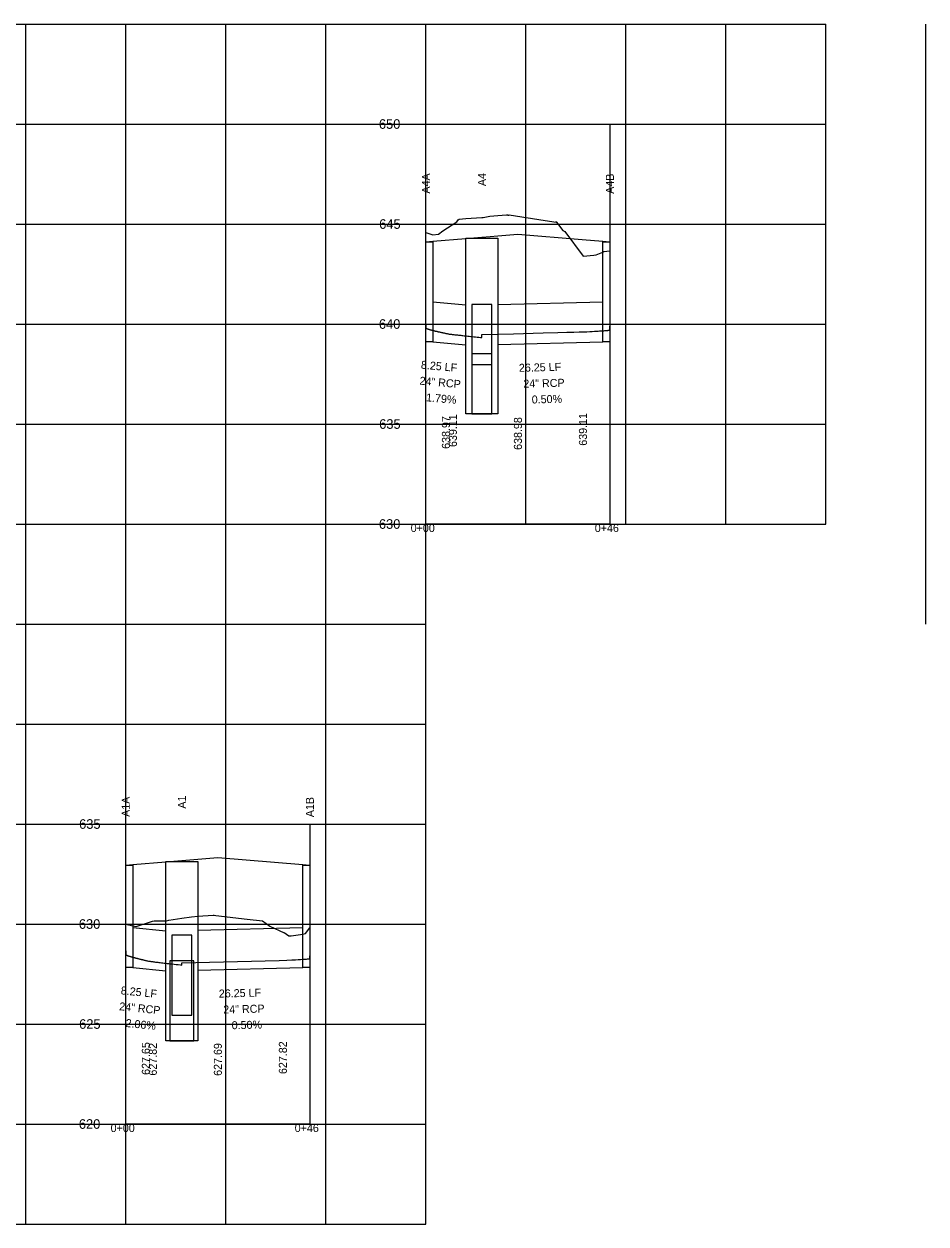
# Model space of a CAD drawing. Extents: x 2252703 to 2264864, y 13787568 to 13790989.
# Drawn here: x 2264638.2 to 2264863.7, y 13787568.1 to 13787868.1 of the extents above; entities that cross this region are included whole.
import ezdxf

# ---------------------------------------------------------------- set-up
doc = ezdxf.new("R2010")
doc.units = 0
for name, color, linetype in [('blank4', 7, 'Continuous'), ('BORD_grid_bottom_major_5int', 7, 'Continuous'), ('D_DRN_PROF_HGL', 7, 'Continuous'), ('D_PROF_1', 7, 'Continuous'), ('D_PROF_NOTES_1', 7, 'Continuous'), ('Default', 7, 'Continuous'), ('Drain_PipeInside', 7, 'Continuous'), ('E_Terrain', 7, 'Continuous'), ('Inlet', 7, 'Continuous'), ('z - Construction', 7, 'Continuous')]:
    doc.layers.add(name, color=color, linetype=linetype)

msp = doc.modelspace()

# ---------------------------------------------------------------- linework, layer by layer
at = {"layer": 'blank4'}
for points in [[(2264738.67, 13787743.09), (2264738.67, 13787843.09), (2264784.67, 13787843.09), (2264784.67, 13787743.09)], [(2264663.67, 13787593.09), (2264663.67, 13787668.09), (2264709.67, 13787668.09), (2264709.67, 13787593.09)]]:
    msp.add_lwpolyline(points, close=True, dxfattribs=at)
at = {"layer": 'BORD_grid_bottom_major_5int'}
for p, q in [((2264413.67, 13787868.09), (2264838.67, 13787868.09)), ((2264638.67, 13787568.09), (2264638.67, 13787868.09)), ((2264663.67, 13787568.09), (2264663.67, 13787868.09)), ((2264688.67, 13787568.09), (2264688.67, 13787868.09)), ((2264713.67, 13787568.09), (2264713.67, 13787868.09)), ((2264738.67, 13787568.09), (2264738.67, 13787868.09)), ((2264763.67, 13787743.09), (2264763.67, 13787868.09)), ((2264788.67, 13787743.09), (2264788.67, 13787868.09)), ((2264813.67, 13787743.09), (2264813.67, 13787868.09)), ((2264838.67, 13787743.09), (2264838.67, 13787868.09)), ((2264863.67, 13787718.09), (2264863.67, 13787868.09)), ((2264413.67, 13787843.09), (2264838.67, 13787843.09)), ((2264413.67, 13787818.09), (2264838.67, 13787818.09)), ((2264413.67, 13787793.09), (2264838.67, 13787793.09)), ((2264413.67, 13787768.09), (2264838.67, 13787768.09)), ((2264413.67, 13787743.09), (2264838.67, 13787743.09)), ((2264413.67, 13787718.09), (2264738.67, 13787718.09)), ((2264413.67, 13787693.09), (2264738.67, 13787693.09)), ((2264413.67, 13787668.09), (2264738.67, 13787668.09)), ((2264413.67, 13787643.09), (2264738.67, 13787643.09)), ((2264413.67, 13787618.09), (2264738.67, 13787618.09)), ((2264413.67, 13787593.09), (2264738.67, 13787593.09)), ((2264413.67, 13787568.09), (2264738.67, 13787568.09))]:
    msp.add_line(p, q, dxfattribs=at)
at = {"layer": 'D_DRN_PROF_HGL'}
for p, q in [((2264752.67, 13787789.71), (2264752.67, 13787790.46)), ((2264677.67, 13787632.83), (2264677.67, 13787633.39))]:
    msp.add_line(p, q, dxfattribs=at)
for points in [[(2264738.67, 13787793.15), (2264738.67, 13787792.13), (2264738.67, 13787792.12), (2264738.67, 13787792.12), (2264738.67, 13787792.11), (2264738.68, 13787792.11), (2264738.68, 13787792.1), (2264738.68, 13787792.1), (2264738.69, 13787792.09), (2264738.69, 13787792.08), (2264738.7, 13787792.08), (2264738.7, 13787792.07), (2264738.71, 13787792.07), (2264738.71, 13787792.06), (2264738.72, 13787792.05), (2264738.73, 13787792.05), (2264738.74, 13787792.04), (2264738.75, 13787792.03), (2264738.76, 13787792.03), (2264738.77, 13787792.02), (2264738.78, 13787792.01), (2264738.8, 13787792.01), (2264738.81, 13787792), (2264738.82, 13787791.99), (2264738.84, 13787791.98), (2264738.85, 13787791.98), (2264738.87, 13787791.97), (2264738.89, 13787791.96), (2264738.91, 13787791.95), (2264738.93, 13787791.94), (2264738.95, 13787791.93), (2264738.97, 13787791.92), (2264738.99, 13787791.92), (2264739.01, 13787791.91), (2264739.04, 13787791.9), (2264739.06, 13787791.89), (2264739.09, 13787791.88), (2264739.11, 13787791.87), (2264739.14, 13787791.86), (2264739.17, 13787791.85), (2264739.2, 13787791.84), (2264739.23, 13787791.83), (2264739.26, 13787791.82), (2264739.3, 13787791.81), (2264739.33, 13787791.79), (2264739.37, 13787791.78), (2264739.4, 13787791.77), (2264739.44, 13787791.76), (2264739.48, 13787791.75), (2264739.52, 13787791.74), (2264739.56, 13787791.72), (2264739.6, 13787791.71), (2264739.65, 13787791.7), (2264739.69, 13787791.68), (2264739.74, 13787791.67), (2264739.79, 13787791.66), (2264739.84, 13787791.64), (2264739.89, 13787791.63), (2264739.94, 13787791.61), (2264740, 13787791.6), (2264740.05, 13787791.59), (2264740.11, 13787791.57), (2264740.17, 13787791.55), (2264740.23, 13787791.54), (2264740.29, 13787791.52), (2264740.36, 13787791.51), (2264740.42, 13787791.49), (2264740.49, 13787791.47), (2264740.56, 13787791.45), (2264740.63, 13787791.44), (2264740.71, 13787791.42), (2264740.78, 13787791.4), (2264740.86, 13787791.38), (2264740.94, 13787791.36), (2264741.02, 13787791.34), (2264741.11, 13787791.32), (2264741.19, 13787791.3), (2264741.28, 13787791.28), (2264741.37, 13787791.26), (2264741.47, 13787791.24), (2264741.56, 13787791.21), (2264741.66, 13787791.19), (2264741.76, 13787791.17), (2264741.87, 13787791.14), (2264741.97, 13787791.12), (2264742.08, 13787791.1), (2264742.2, 13787791.07), (2264742.31, 13787791.04), (2264742.43, 13787791.02), (2264742.56, 13787790.99), (2264742.68, 13787790.96), (2264742.81, 13787790.94), (2264742.94, 13787790.91), (2264743.08, 13787790.88), (2264743.22, 13787790.85), (2264743.37, 13787790.82), (2264743.52, 13787790.78), (2264743.67, 13787790.75), (2264743.83, 13787790.72), (2264743.99, 13787790.68), (2264744.16, 13787790.65), (2264744.33, 13787790.61), (2264744.5, 13787790.58), (2264744.69, 13787790.56), (2264744.87, 13787790.54), (2264745.07, 13787790.52), (2264745.27, 13787790.5), (2264745.47, 13787790.47), (2264745.68, 13787790.45), (2264745.9, 13787790.42), (2264746.13, 13787790.4), (2264746.36, 13787790.37), (2264746.6, 13787790.35), (2264746.85, 13787790.32), (2264747.11, 13787790.29), (2264747.37, 13787790.26), (2264747.65, 13787790.23), (2264747.93, 13787790.2), (2264748.23, 13787790.17), (2264748.53, 13787790.14), (2264748.85, 13787790.1), (2264749.18, 13787790.07), (2264749.52, 13787790.03), (2264749.87, 13787790), (2264750.24, 13787789.96), (2264750.63, 13787789.92), (2264751.03, 13787789.88), (2264751.45, 13787789.84), (2264751.89, 13787789.79), (2264752.34, 13787789.75), (2264752.67, 13787789.71)], [(2264752.67, 13787790.46), (2264760.6, 13787790.67), (2264768.01, 13787790.86), (2264771.61, 13787790.95), (2264773.94, 13787791.02), (2264775.63, 13787791.06), (2264776.94, 13787791.1), (2264778, 13787791.13), (2264778.87, 13787791.16), (2264779.61, 13787791.2), (2264780.24, 13787791.24), (2264780.79, 13787791.27), (2264781.27, 13787791.3), (2264781.69, 13787791.32), (2264782.06, 13787791.35), (2264782.39, 13787791.37), (2264782.68, 13787791.39), (2264782.94, 13787791.41), (2264783.17, 13787791.42), (2264783.38, 13787791.44), (2264783.57, 13787791.45), (2264783.73, 13787791.47), (2264783.88, 13787791.48), (2264784.01, 13787791.49), (2264784.12, 13787791.5), (2264784.23, 13787791.51), (2264784.31, 13787791.52), (2264784.39, 13787791.53), (2264784.46, 13787791.54), (2264784.51, 13787791.55), (2264784.56, 13787791.55), (2264784.6, 13787791.56), (2264784.63, 13787791.57), (2264784.65, 13787791.57), (2264784.66, 13787791.58), (2264784.67, 13787791.58), (2264784.67, 13787791.59), (2264784.67, 13787792.54)], [(2264663.67, 13787636.41), (2264663.67, 13787635.46), (2264663.67, 13787635.45), (2264663.67, 13787635.45), (2264663.68, 13787635.44), (2264663.68, 13787635.44), (2264663.68, 13787635.43), (2264663.69, 13787635.42), (2264663.69, 13787635.42), (2264663.7, 13787635.41), (2264663.7, 13787635.41), (2264663.71, 13787635.4), (2264663.72, 13787635.39), (2264663.73, 13787635.39), (2264663.74, 13787635.38), (2264663.74, 13787635.37), (2264663.76, 13787635.37), (2264663.77, 13787635.36), (2264663.78, 13787635.35), (2264663.79, 13787635.34), (2264663.8, 13787635.33), (2264663.82, 13787635.33), (2264663.83, 13787635.32), (2264663.85, 13787635.31), (2264663.87, 13787635.3), (2264663.88, 13787635.29), (2264663.9, 13787635.28), (2264663.92, 13787635.28), (2264663.94, 13787635.27), (2264663.96, 13787635.26), (2264663.99, 13787635.25), (2264664.01, 13787635.24), (2264664.03, 13787635.23), (2264664.06, 13787635.22), (2264664.09, 13787635.21), (2264664.11, 13787635.2), (2264664.14, 13787635.19), (2264664.17, 13787635.17), (2264664.2, 13787635.16), (2264664.23, 13787635.15), (2264664.27, 13787635.14), (2264664.3, 13787635.13), (2264664.34, 13787635.11), (2264664.38, 13787635.1), (2264664.41, 13787635.09), (2264664.45, 13787635.08), (2264664.49, 13787635.06), (2264664.54, 13787635.05), (2264664.58, 13787635.04), (2264664.63, 13787635.02), (2264664.67, 13787635.01), (2264664.72, 13787634.99), (2264664.77, 13787634.98), (2264664.82, 13787634.96), (2264664.87, 13787634.94), (2264664.93, 13787634.93), (2264664.99, 13787634.91), (2264665.04, 13787634.89), (2264665.1, 13787634.88), (2264665.17, 13787634.86), (2264665.23, 13787634.84), (2264665.3, 13787634.82), (2264665.37, 13787634.8), (2264665.44, 13787634.78), (2264665.51, 13787634.76), (2264665.58, 13787634.74), (2264665.66, 13787634.72), (2264665.74, 13787634.7), (2264665.82, 13787634.68), (2264665.9, 13787634.66), (2264665.99, 13787634.63), (2264666.08, 13787634.61), (2264666.17, 13787634.59), (2264666.27, 13787634.56), (2264666.36, 13787634.54), (2264666.47, 13787634.51), (2264666.57, 13787634.49), (2264666.68, 13787634.46), (2264666.79, 13787634.43), (2264666.9, 13787634.4), (2264667.02, 13787634.37), (2264667.14, 13787634.34), (2264667.26, 13787634.31), (2264667.39, 13787634.28), (2264667.53, 13787634.25), (2264667.66, 13787634.21), (2264667.81, 13787634.18), (2264667.95, 13787634.15), (2264668.1, 13787634.11), (2264668.26, 13787634.07), (2264668.42, 13787634.03), (2264668.59, 13787633.99), (2264668.76, 13787633.95), (2264668.94, 13787633.91), (2264669.12, 13787633.87), (2264669.32, 13787633.82), (2264669.51, 13787633.79), (2264669.72, 13787633.76), (2264669.93, 13787633.73), (2264670.15, 13787633.71), (2264670.38, 13787633.68), (2264670.62, 13787633.65), (2264670.87, 13787633.62), (2264671.12, 13787633.59), (2264671.39, 13787633.55), (2264671.67, 13787633.52), (2264671.96, 13787633.49), (2264672.26, 13787633.45), (2264672.58, 13787633.41), (2264672.91, 13787633.37), (2264673.26, 13787633.33), (2264673.62, 13787633.29), (2264674, 13787633.25), (2264674.4, 13787633.2), (2264674.82, 13787633.15), (2264675.26, 13787633.1), (2264675.73, 13787633.05), (2264676.22, 13787632.99), (2264676.74, 13787632.93), (2264677.3, 13787632.87), (2264677.67, 13787632.83)], [(2264677.67, 13787633.39), (2264702.02, 13787634), (2264703.92, 13787634.05), (2264705.17, 13787634.12), (2264706.07, 13787634.17), (2264706.76, 13787634.21), (2264707.3, 13787634.24), (2264707.74, 13787634.27), (2264708.11, 13787634.29), (2264708.41, 13787634.31), (2264708.66, 13787634.33), (2264708.86, 13787634.34), (2264709.04, 13787634.36), (2264709.18, 13787634.37), (2264709.3, 13787634.38), (2264709.4, 13787634.39), (2264709.48, 13787634.4), (2264709.55, 13787634.41), (2264709.59, 13787634.41), (2264709.63, 13787634.42), (2264709.65, 13787634.43), (2264709.66, 13787634.43), (2264709.66, 13787634.44), (2264709.67, 13787634.44), (2264709.67, 13787635.13)]]:
    msp.add_lwpolyline(points, dxfattribs=at)
at = {"layer": 'D_PROF_1'}
for points in [[(2264738.67, 13787813.66), (2264740.42, 13787813.8), (2264740.42, 13787813.8), (2264748.67, 13787814.48), (2264748.67, 13787814.48), (2264752.67, 13787814.81), (2264752.67, 13787814.81), (2264754.77, 13787814.98), (2264756.67, 13787815.13), (2264756.67, 13787815.13), (2264761.67, 13787815.54), (2264777.77, 13787814.22), (2264782.92, 13787813.8), (2264782.92, 13787813.8), (2264784.67, 13787813.66)], [(2264663.67, 13787657.83), (2264665.42, 13787657.97), (2264665.42, 13787657.97), (2264673.67, 13787658.65), (2264673.67, 13787658.65), (2264677.67, 13787658.97), (2264677.67, 13787658.97), (2264681.67, 13787659.3), (2264681.67, 13787659.3), (2264686.67, 13787659.71), (2264686.67, 13787659.71), (2264707.92, 13787657.97), (2264707.92, 13787657.97), (2264709.67, 13787657.83), (2264709.67, 13787657.83)]]:
    msp.add_lwpolyline(points, dxfattribs=at)
at = {"layer": 'Drain_PipeInside'}
for p, q in [((2264740.42, 13787798.66), (2264748.67, 13787797.92)), ((2264756.67, 13787798), (2264782.92, 13787798.66)), ((2264740.42, 13787788.66), (2264748.67, 13787787.92)), ((2264756.67, 13787788), (2264782.92, 13787788.66)), ((2264665.42, 13787642.21), (2264673.67, 13787641.36)), ((2264681.67, 13787641.56), (2264707.92, 13787642.21)), ((2264665.42, 13787632.21), (2264673.67, 13787631.36)), ((2264681.67, 13787631.56), (2264707.92, 13787632.21))]:
    msp.add_line(p, q, dxfattribs=at)
for points in [[(2264750.17, 13787782.94), (2264755.17, 13787782.94), (2264755.17, 13787797.94), (2264750.17, 13787797.94)], [(2264750.17, 13787770.61), (2264755.17, 13787770.61), (2264755.17, 13787785.61), (2264750.17, 13787785.61)], [(2264675.17, 13787620.32), (2264680.17, 13787620.32), (2264680.17, 13787640.32), (2264675.17, 13787640.32)], [(2264674.67, 13787613.88), (2264680.67, 13787613.88), (2264680.67, 13787633.88), (2264674.67, 13787633.88)]]:
    msp.add_lwpolyline(points, close=True, dxfattribs=at)
at = {"layer": 'E_Terrain'}
for points in [[(2264738.67, 13787815.97), (2264740.4, 13787815.42), (2264740.42, 13787815.42), (2264740.42, 13787815.42), (2264741.79, 13787815.59), (2264742.93, 13787816.38), (2264746.39, 13787818.61), (2264746.71, 13787819.12), (2264746.96, 13787819.33), (2264748.67, 13787819.43), (2264748.67, 13787819.43), (2264752.67, 13787819.68), (2264752.67, 13787819.68), (2264753.02, 13787819.7), (2264754.62, 13787820.02), (2264756.67, 13787820.2), (2264756.67, 13787820.2), (2264758.79, 13787820.38), (2264759.05, 13787820.35), (2264759.13, 13787820.34), (2264759.4, 13787820.34), (2264759.48, 13787820.36), (2264768.49, 13787818.97), (2264771.24, 13787818.58), (2264771.24, 13787818.69), (2264771.32, 13787818.52), (2264772.93, 13787816.45), (2264773.37, 13787816.23), (2264778.02, 13787810.05), (2264780.65, 13787810.34), (2264781.26, 13787810.36), (2264782.92, 13787811.08), (2264782.92, 13787811.08), (2264783.15, 13787811.18), (2264784.67, 13787811.42)], [(2264663.67, 13787643.05), (2264665.42, 13787642.66), (2264665.42, 13787642.66), (2264666.23, 13787642.48), (2264670.36, 13787643.8), (2264670.75, 13787643.85), (2264673.67, 13787643.91), (2264673.67, 13787643.91), (2264673.8, 13787643.92), (2264674.41, 13787644.09), (2264677.67, 13787644.55), (2264677.67, 13787644.55), (2264680.12, 13787644.89), (2264681.67, 13787645.01), (2264681.67, 13787645.01), (2264685.5, 13787645.31), (2264685.75, 13787645.27), (2264686.2, 13787645.24), (2264693.99, 13787644.29), (2264697.83, 13787643.85), (2264699.68, 13787642.55), (2264703.21, 13787640.9), (2264703.26, 13787640.97), (2264704.43, 13787640.17), (2264705.03, 13787640.17), (2264707.92, 13787640.59), (2264707.92, 13787640.59), (2264708.55, 13787640.68), (2264709.67, 13787642.12)]]:
    msp.add_lwpolyline(points, dxfattribs=at)
at = {"layer": 'Inlet'}
for points in [[(2264748.67, 13787814.54), (2264756.67, 13787814.54), (2264756.67, 13787770.61), (2264748.67, 13787770.61)], [(2264738.67, 13787813.66), (2264740.42, 13787813.66), (2264740.42, 13787788.66), (2264738.67, 13787788.66)], [(2264782.92, 13787813.66), (2264784.67, 13787813.66), (2264784.67, 13787788.66), (2264782.92, 13787788.66)], [(2264673.67, 13787658.71), (2264681.67, 13787658.71), (2264681.67, 13787613.88), (2264673.67, 13787613.88)], [(2264663.67, 13787657.83), (2264665.42, 13787657.83), (2264665.42, 13787632.21), (2264663.67, 13787632.21)], [(2264707.92, 13787657.83), (2264709.67, 13787657.83), (2264709.67, 13787632.21), (2264707.92, 13787632.21)]]:
    msp.add_lwpolyline(points, close=True, dxfattribs=at)
at = {"layer": 'z - Construction'}
for p, q in [((2264738.67, 13787818.09), (2264784.67, 13787818.09)), ((2264738.67, 13787793.09), (2264784.67, 13787793.09)), ((2264738.67, 13787768.09), (2264784.67, 13787768.09)), ((2264663.67, 13787643.09), (2264709.67, 13787643.09)), ((2264663.67, 13787618.09), (2264709.67, 13787618.09))]:
    msp.add_line(p, q, dxfattribs=at)

# ---------------------------------------------------------------- texts
at = {"layer": 'D_PROF_NOTES_1'}
for s, rotation, p in [('A4A', 90, (2264739.67, 13787825.7)), ('A4', 90, (2264753.67, 13787827.57)), ('A4B', 90, (2264785.67, 13787825.64)), ('8.25 LF', 354.8745, (2264737.36, 13787781.94)), ('26.25 LF', 1.4321, (2264761.94, 13787781.13)), ('24" RCP', 354.8745, (2264737.02, 13787777.95)), ('24" RCP', 1.4321, (2264763.05, 13787777.16)), ('1.79%', 354.8745, (2264738.66, 13787773.79)), ('0.50%', 1.4321, (2264765.15, 13787773.21)), ('638.97', 90, (2264744.67, 13787761.88)), ('639.11', 90, (2264746.42, 13787762.34)), ('638.98', 90, (2264762.67, 13787761.62)), ('639.11', 90, (2264778.92, 13787762.66)), ('A1A', 90, (2264664.67, 13787669.87)), ('A1', 90, (2264678.67, 13787671.94)), ('A1B', 90, (2264710.67, 13787669.8)), ('8.25 LF', 354.1176, (2264662.33, 13787625.54)), ('26.25 LF', 1.4321, (2264686.94, 13787624.69)), ('24" RCP', 354.1176, (2264661.94, 13787621.56)), ('24" RCP', 1.4321, (2264688.05, 13787620.71)), ('2.06%', 354.1176, (2264663.53, 13787617.37)), ('0.50%', 1.4321, (2264690.15, 13787616.77)), ('627.65', 90, (2264669.67, 13787605.37)), ('627.82', 90, (2264671.42, 13787605.19)), ('627.69', 90, (2264687.67, 13787605.13)), ('627.82', 90, (2264703.92, 13787605.58))]:
    msp.add_text(s, height=2, rotation=rotation, dxfattribs=at).set_placement(p)
at = {"layer": 'Default'}
for s, height, p in [('650', 2.4, (2264726.93, 13787841.89)), ('645', 2.4, (2264727, 13787816.89)), ('640', 2.4, (2264726.93, 13787791.89)), ('635', 2.4, (2264727, 13787766.89)), ('630', 2.4, (2264726.93, 13787741.89)), ('0+00', 2, (2264734.87, 13787741.09)), ('0+46', 2, (2264780.88, 13787741.09)), ('635', 2.4, (2264652, 13787666.89)), ('630', 2.4, (2264651.93, 13787641.89)), ('625', 2.4, (2264652, 13787616.89)), ('620', 2.4, (2264651.93, 13787591.89)), ('0+00', 2, (2264659.87, 13787591.09)), ('0+46', 2, (2264705.88, 13787591.09))]:
    msp.add_text(s, height=height, dxfattribs=at).set_placement(p)

doc.saveas('drawing.dxf')
